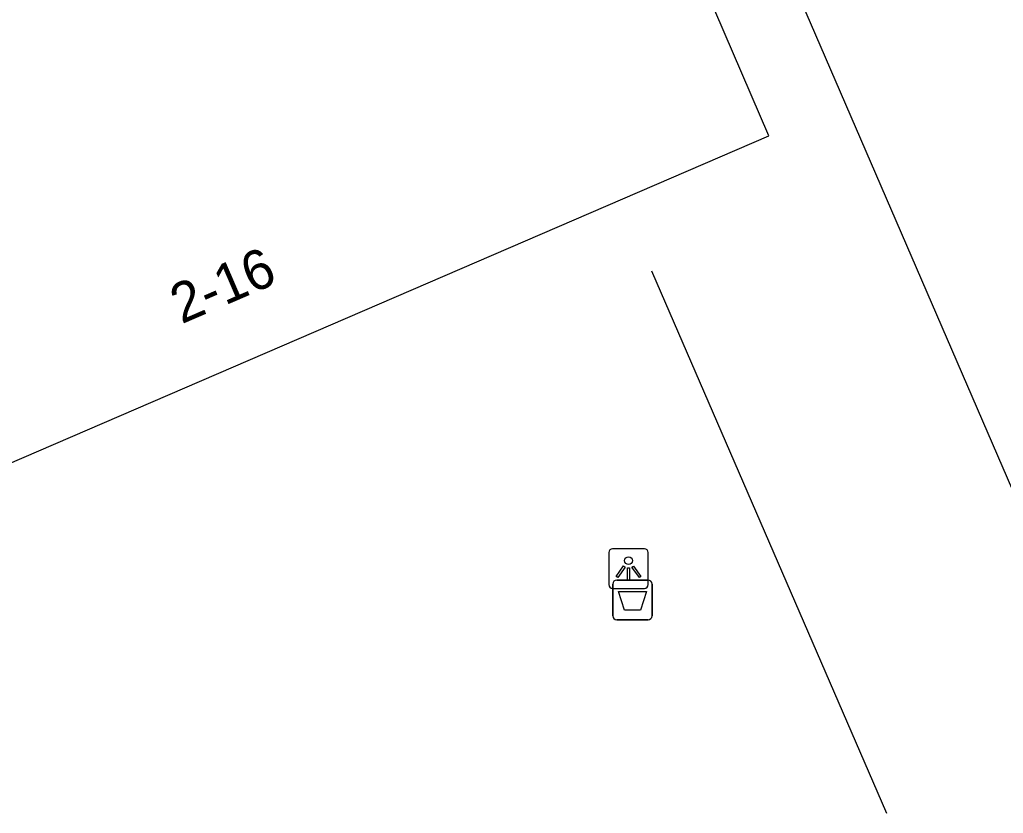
# Model space of a CAD drawing. Extents: x 155640 to 156810, y 382822 to 384046.
# Drawn here: x 156667.33 to 156692.13, y 383672.43 to 383692.43 of the extents above; entities that cross this region are included whole.
import ezdxf

# ---------------------------------------------------------------- set-up
doc = ezdxf.new("R2010")
doc.units = 0
for name, color, linetype in [('IMGEO_Afvalbak', 7, 'Continuous'), ('IMGEO_Lichtpunt', 7, 'Continuous'), ('IMGEO_Lijnafwatering', 7, 'Continuous'), ('IMGEO_Pand', 7, 'Continuous'), ('IMGEO_Pand_nummerreeks', 7, 'Continuous')]:
    doc.layers.add(name, color=color, linetype=linetype)

msp = doc.modelspace()

# ---------------------------------------------------------------- linework, layer by layer
at = {"layer": 'IMGEO_Afvalbak'}
for p, q in [((156682.282, 383677.406), (156682.282, 383678.206)), ((156682.282, 383678.206), (156682.282, 383677.406)), ((156682.382, 383678.306), (156683.172, 383678.306)), ((156683.172, 383678.306), (156682.382, 383678.306)), ((156683.272, 383678.206), (156683.272, 383677.406)), ((156683.272, 383677.406), (156683.272, 383678.206)), ((156683.172, 383677.306), (156682.382, 383677.306)), ((156682.382, 383677.306), (156683.172, 383677.306))]:
    msp.add_line(p, q, dxfattribs=at)
msp.add_lwpolyline([(156682.425, 383678.02), (156683.129, 383678.02), (156682.98, 383677.55), (156682.574, 383677.55), (156682.425, 383678.02)], dxfattribs=at)
for centre, start, end in [((156682.382, 383678.206), 90, 180), ((156682.382, 383678.206), 90, 180), ((156683.172, 383678.206), 0, 90), ((156683.172, 383678.206), 360, 90), ((156682.382, 383677.406), 180, 270), ((156682.382, 383677.406), 180, 270), ((156683.172, 383677.406), 270, 0), ((156683.172, 383677.406), 270, 0)]:
    msp.add_arc(centre, 0.1, start, end, dxfattribs=at)
at = {"layer": 'IMGEO_Lichtpunt'}
for p, q in [((156683.082, 383679.094), (156682.274, 383679.094)), ((156683.082, 383679.094), (156682.274, 383679.094)), ((156682.18, 383678.999), (156682.18, 383678.192)), ((156682.18, 383678.999), (156682.18, 383678.192)), ((156683.176, 383678.192), (156683.176, 383678.999)), ((156683.176, 383678.192), (156683.176, 383678.999)), ((156682.274, 383678.098), (156683.082, 383678.098)), ((156682.274, 383678.098), (156683.082, 383678.098))]:
    msp.add_line(p, q, dxfattribs=at)
for points in [[(156682.554, 383678.663), (156682.593, 383678.635), (156682.405, 383678.373), (156682.367, 383678.4), (156682.554, 383678.663)], [(156682.656, 383678.615), (156682.703, 383678.615), (156682.703, 383678.293), (156682.656, 383678.293), (156682.656, 383678.615)], [(156682.766, 383678.635), (156682.804, 383678.662), (156682.991, 383678.4), (156682.952, 383678.372), (156682.766, 383678.635)]]:
    msp.add_lwpolyline(points, dxfattribs=at)
msp.add_circle((156682.679, 383678.797), 0.0994, dxfattribs=at)
for centre, start, end in [((156682.274, 383678.999), 90, 180), ((156682.274, 383678.999), 90, 180), ((156683.082, 383678.999), 0, 90), ((156683.082, 383678.999), 0, 90), ((156682.274, 383678.192), 180, 270), ((156682.274, 383678.192), 180, 270), ((156683.082, 383678.192), 270, 0), ((156683.082, 383678.192), 270, 360)]:
    msp.add_arc(centre, 0.0946, start, end, dxfattribs=at)
at = {"layer": 'IMGEO_Lijnafwatering'}
for points in [[(156680.485, 383708.012), (156687.636, 383691.485)], [(156687.636, 383691.485), (156694.786, 383674.957)], [(156683.257, 383686.1), (156689.182, 383672.428)]]:
    msp.add_lwpolyline(points, dxfattribs=at)
at = {"layer": 'IMGEO_Pand'}
msp.add_lwpolyline([(156652.408, 383686.743), (156663.435, 383679.681), (156664.119, 383679.976), (156686.219, 383689.506), (156678.78, 383706.772)], dxfattribs=at)

# ---------------------------------------------------------------- texts
at = {"layer": 'IMGEO_Pand_nummerreeks'}
msp.add_text('2-16', height=1, rotation=23.3251, dxfattribs=at).set_placement((156671.409, 383684.753))

doc.saveas('drawing.dxf')
